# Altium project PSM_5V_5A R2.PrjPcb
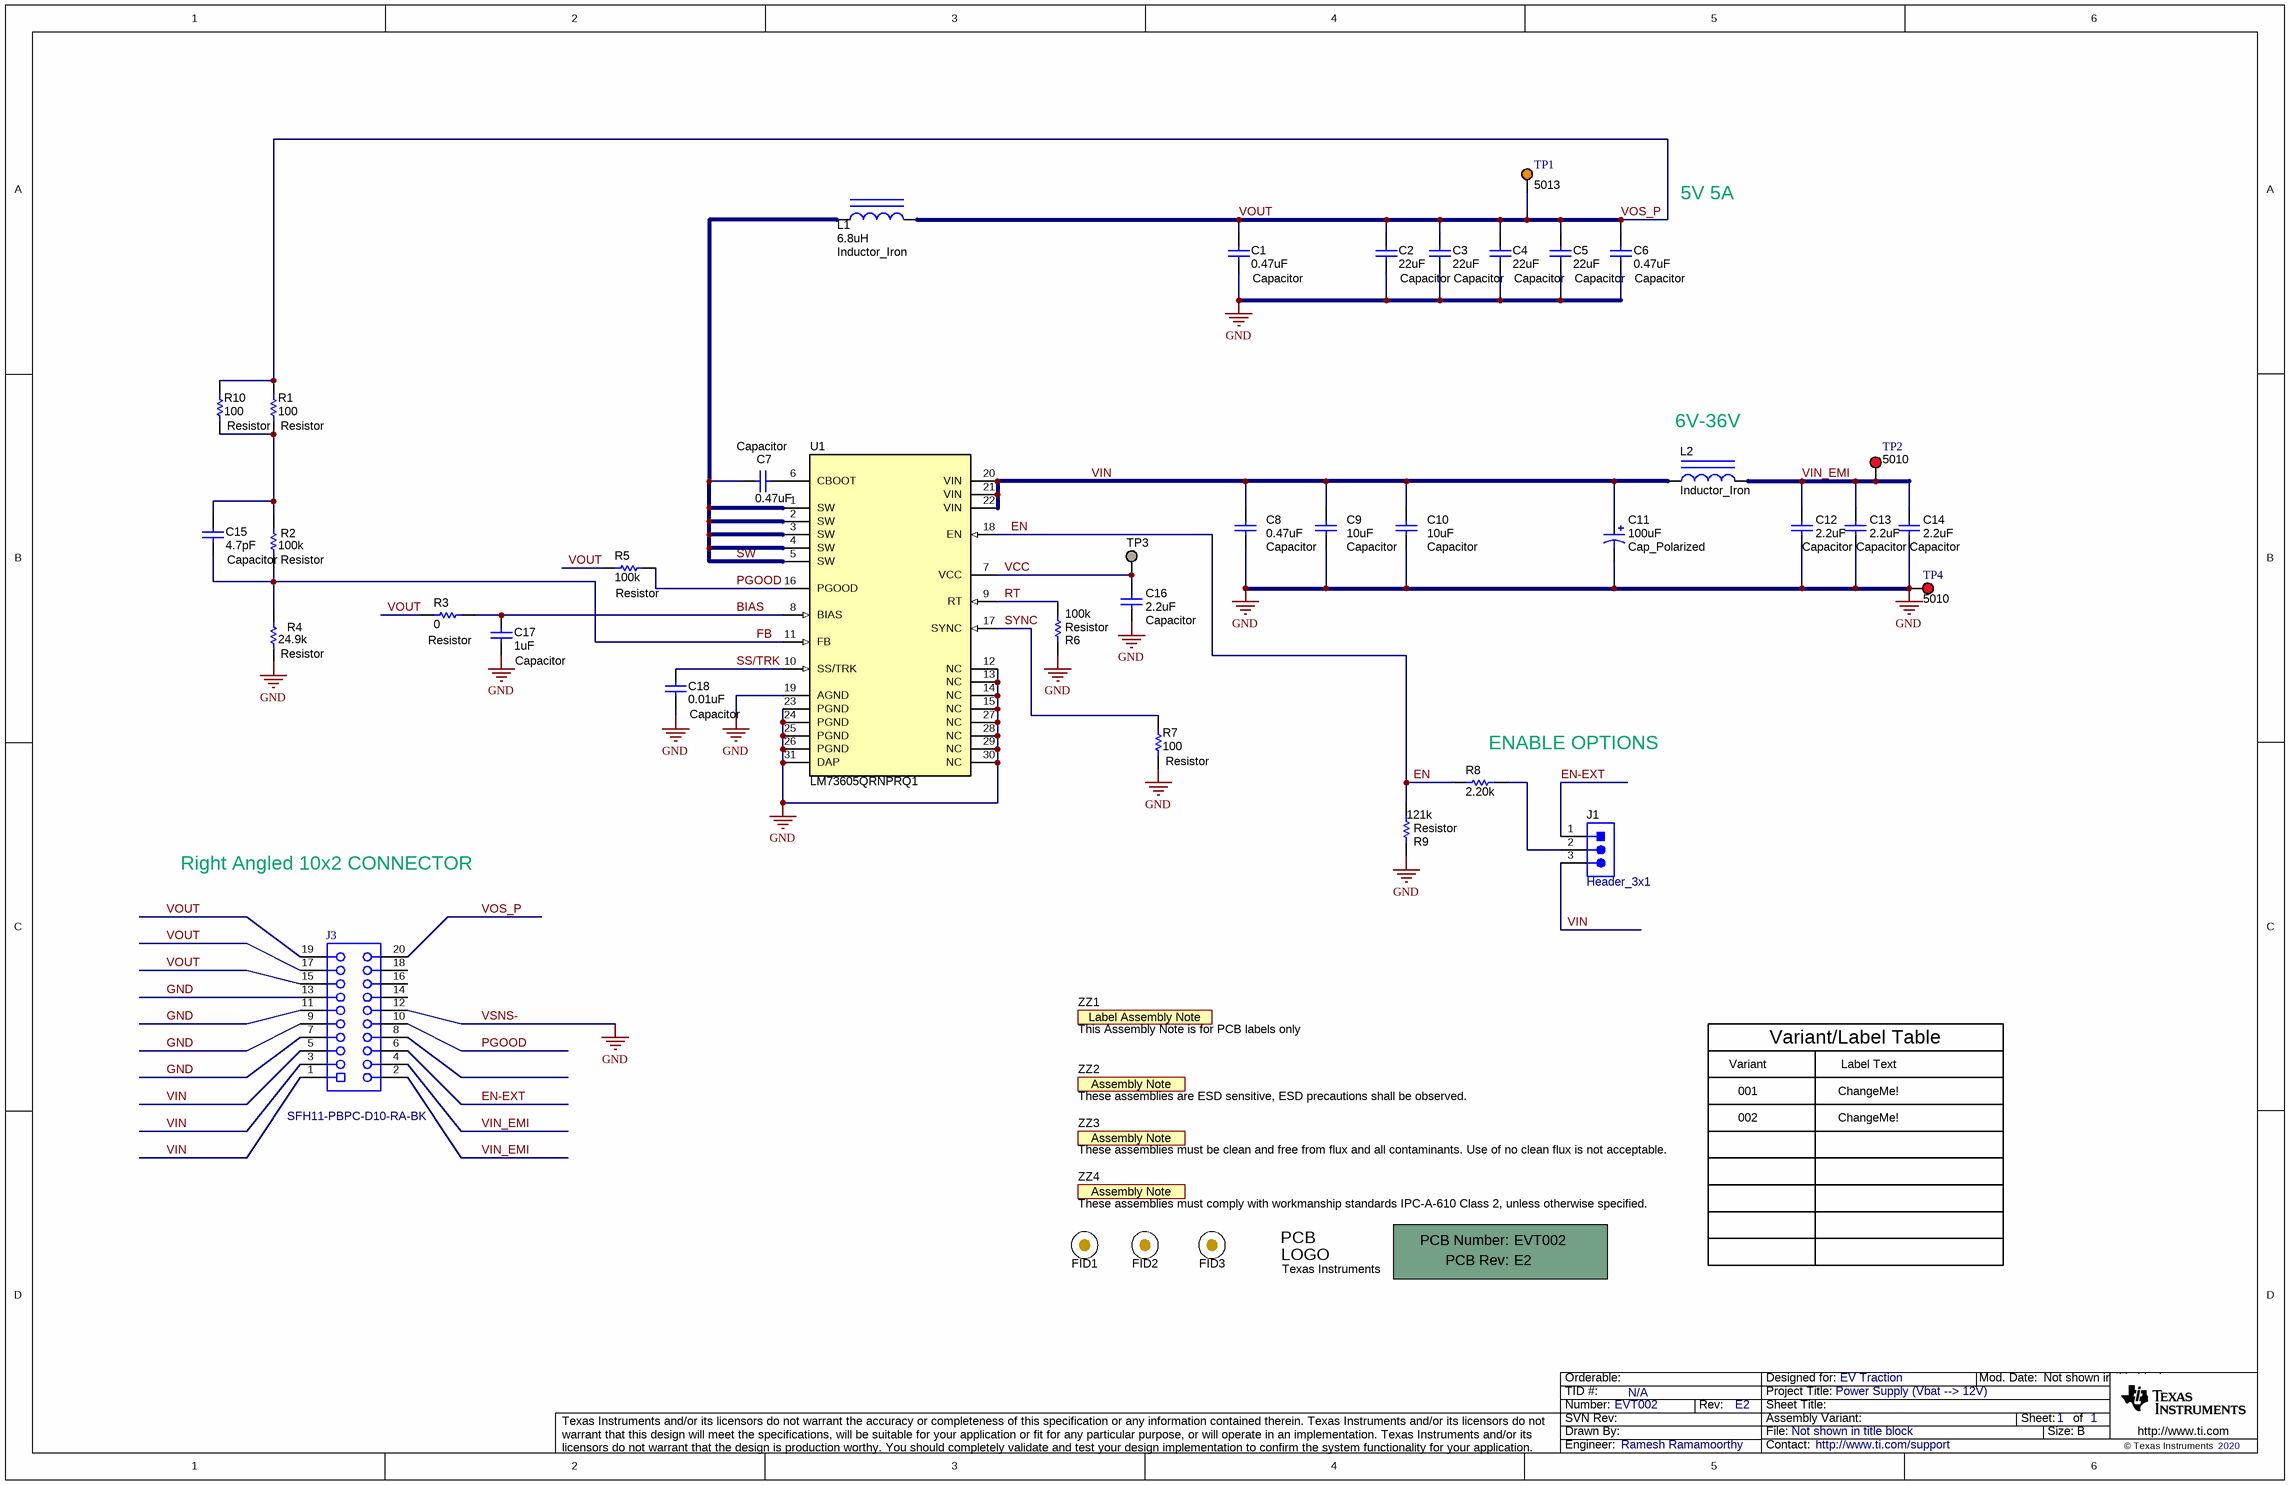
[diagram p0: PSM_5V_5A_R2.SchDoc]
CopyrightYear: 2020; PCB_Layout: Ramesh Ramamoorthy; PCB_Rev: E2; PRJ_Customer: EV Traction; PRJ_Engineer: Ramesh Ramamoorthy; PRJ_Number: EVT002; PRJ_Title: Power Supply (Vbat --> 12V); SCH_Rev: E2; TechSupport: http://www.ti.com/support; TID: N/A
1 sheet, 46 parts. Net scope: global (net labels, ports and power ports of the same name join across sheets).
Board file: PSM_5V_5A_R2_r3.PcbDoc

## Sheet PSM_5V_5A_R2.SchDoc
size 431 x 279 mm; Date: Not shown in title block; ApprovedBy: Not shown in title block; CheckedBy: Not shown in title block; Author: Not shown in title block; CompanyName: Not shown in title block; Engineer: Not shown in title block; Organization: Not shown in title block; Address1: Not shown in title block; Address2: Not shown in title block; Address3: Not shown in title block; Address4: Not shown in title block; DocumentNumber: 1; Revision: Use project parameter SCH_Rev; SheetNumber: 1; SheetTotal: 1; PageSetup: Record=PageOptions¦CenterHorizontal=True¦CenterVertical=True¦PrintScale=1.00¦XCorrection=1.00¦YCorrection=1.00¦PrintKind=0¦BorderSize=5000000¦LeftOffset=0¦BottomOffset=0¦Orientation=2¦PaperLength=1000¦PaperWidth=1000¦Scale=100¦PaperSource=15¦PrintQuality=600¦MediaType=1¦DitherType=10¦PaperKind=Letter¦PrintScaleMode=1

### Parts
!PCB1  Printed Circuit Board  (value not drawn)  (mechanical)
C1  Capacitor  ValueDisplayed: 0.47uF  [0805_HV]
C2  Capacitor  ValueDisplayed: 22uF  [1210_270]
C3  Capacitor  ValueDisplayed: 22uF  [1210_270]
C4  Capacitor  ValueDisplayed: 22uF  [1210_270]
C5  Capacitor  ValueDisplayed: 22uF  [1210_270]
C6  Capacitor  ValueDisplayed: 0.47uF  [0805_HV]
C7  Capacitor  ValueDisplayed: 0.47uF  [0603]
C8  Capacitor  ValueDisplayed: 0.47uF  [0805_HV]
C9  Capacitor  ValueDisplayed: 10uF  [1210_270]
C10  Capacitor  ValueDisplayed: 10uF  [1210_270]
C11  Cap_Polarized  ValueDisplayed: 100uF  [SM_RADIAL_G]
C12  Capacitor  ValueDisplayed: 2.2uF  [1206_180]
C13  Capacitor  ValueDisplayed: 2.2uF  [1206_180]
C14  Capacitor  ValueDisplayed: 2.2uF  [1206_180]
C15  Capacitor  ValueDisplayed: 4.7pF  [0603]
C16  Capacitor  ValueDisplayed: 2.2uF  [0603]
C17  Capacitor  ValueDisplayed: 1uF  [0603]
C18  Capacitor  ValueDisplayed: 0.01uF  [0603]
FID1  Fiducial  [Fiducial10-20]  (value not drawn)
FID2  Fiducial  [Fiducial10-20]  (value not drawn)
FID3  Fiducial  [Fiducial10-20]  (value not drawn)
J1  Header_3x1  [Samtec_HTSW-103-07-G-S]
J3  SFH11-PBPC-D10-RA-BK  [Sullins_SFH11-xxxC-D10-RA]
L1  Inductor_Iron  ValueDisplayed: 6.8uH  [XAL7070]
L2  Inductor_Iron  [XAL7030]
Logo1  Texas Instruments  [TI_Symbol_Overlay_Small]  (no BOM)
R1  Resistor  ValueDisplayed: 100  [0805_HV]
R2  Resistor  ValueDisplayed: 100k  [0603]
R3  Resistor  ValueDisplayed: 0  [0603]
R4  Resistor  ValueDisplayed: 24.9k  [0603]
R5  Resistor  ValueDisplayed: 100k  [0603]
R6  Resistor  ValueDisplayed: 100k  [0603]
R7  Resistor  ValueDisplayed: 100  [0603]
R8  ValueDisplayed: 2.20k  [0805_HV]  (hidden comment: RG2012P-222-B-T5)
R9  Resistor  ValueDisplayed: 121k  [0805_HV]
R10  Resistor  ValueDisplayed: 100  [0805_HV]
TP1  5013  [Keystone5013]
TP2  5010  [Keystone5010]
TP3  TP_H0.45P0.75  [TP_H045P075]  (value not drawn)  (no BOM)
TP4  5010  [Keystone5010]
U1  LM73605QRNPRQ1  [RNP0030A]
ZZ1  This Assembly Note is for PCB labels only  [AssemblyNoteLabel]  (no BOM)
ZZ2  These assemblies are ESD sensitive, ESD precautions shall be observed.  [AssemblyNote]  (no BOM)
ZZ3  These assemblies must be clean and free from flux and all contaminants. Use of no clean flux is not acceptable.  [AssemblyNote]  (no BOM)
ZZ4  These assemblies must comply with workmanship standards IPC-A-610 Class 2, unless otherwise specified.  [AssemblyNote]  (no BOM)

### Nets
GND: C1.1 C2.2 C3.2 C4.2 C5.2 C6.1 C8.1 C9.1 C10.1 C11.2(-) C12.2 C13.2 C14.2 C16.2 C17.2 C18.2 J3.7 J3.9 J3.11 J3.12 J3.13 R4.1 R6.2 R7.1 R9.1 TP4.1 U1.12(NC) U1.13(NC) U1.14(NC) U1.15(NC) U1.19(AGND) U1.23(PGND) U1.24(PGND) U1.25(PGND) U1.26(PGND) U1.27(NC) U1.28(NC) U1.29(NC) U1.30(NC) U1.31(DAP)  [also labelled VSNS-]
BIAS: C17.1 R3.2 U1.8(BIAS)
EN: R8.1 R9.2 U1.18(EN)
EN-EXT: J1.1 J3.6
FB: C15.2 R2.1 R4.2 U1.11(FB)
PGOOD: J3.10 R5.2 U1.16(PGOOD)
RT: R6.1 U1.9(RT)
SS/TRK: C18.1 U1.10(SS/TRK)
SW: C7.1 L1.1 U1.1(SW) U1.2(SW) U1.3(SW) U1.4(SW) U1.5(SW)
SYNC: R7.2 U1.17(SYNC)
VCC: C16.1 TP3.1 U1.7(VCC)
VIN: C8.2 C9.2 C10.2 C11.1(+) J1.3 J3.1 J3.3 J3.5 L2.1 U1.20(VIN) U1.21(VIN) U1.22(VIN)
VIN_EMI: C12.1 C13.1 C14.1 J3.2 J3.4 L2.2 TP2.1
VOS_P: C1.2 C2.1 C3.1 C4.1 C5.1 C6.2 J3.15 J3.17 J3.19 J3.20 L1.2 R1.2 R3.1 R5.1 R10.2 TP1.1  [also labelled VOUT]
NetC7_2: C7.2 U1.6(CBOOT)
NetC15_1: C15.1 R1.1 R2.2 R10.1
NetJ1_2: J1.2 R8.2

Not connected (* = marked no-connect by the designer): J3 8 14 16 18

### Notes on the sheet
- 5V 5A
- (near L2) 6V-36V
- (near R8) ENABLE OPTIONS
- Right Angled 10x2 CONNECTOR
- Variant/Label Table
- Variant
- 001
- Label Text
- ChangeMe!
- 002

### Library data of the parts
!PCB1 = CMP-0003618-2: Manufacturer: Any; PartNumber: EVT002
C1 C6 C8 = CMP-0008357-2: CAP, CERM, 0.47 uF, 50 V, +/- 10%, X7R, 0805; PartNumber: GRM21BR71H474KA88L; Manufacturer: MuRata; Polarized: N; Value: 0.47uF; U/M: EA; Cap_F: 470nF; Value1: Unknown; VDC_V: 50V; TaMin_C: -55°C; TaMax_C: 125°C; Cap_Case: 0805; AEC Category: Q200; SizeArea_mm2: 2.5; SizeAreaWB_mm2: 6.75; SizeX_mm: 2; SizeY_mm: 1.25; SizeZ_mm: 1.45
C2-C5 = CMP-0009222-2: CAP, CERM, 22 uF, 16 V, +/- 10%, X7R, 1210; PartNumber: GRM32ER71C226KE18L; Manufacturer: MuRata; Polarized: N; Value: 22uF; U/M: EA; Cap_F: 22µF; ESR_ohm: 3m; Value1: 0.003 ohm; VDC_V: 16V; TaMin_C: -55°C; TaMax_C: 125°C; Cap_Case: 1210; AEC Category: Q200; SizeArea_mm2: 8; SizeAreaWB_mm2: 14.7; SizeX_mm: 3.2; SizeY_mm: 2.5; SizeZ_mm: 2.7
C7 = CMP-0007346-5: CAP, CERM, 0.47 uF, 25 V, +/- 10%, X5R, 0603; PartNumber: GRM188R61E474KA12D; Manufacturer: MuRata; Polarized: N; Value: 0.47uF; U/M: EA; Cap_F: 470nF; Value1: Unknown; VDC_V: 25V; TaMin_C: -55°C; TaMax_C: 85°C; AEC Category: Q200; SizeArea_mm2: 1.28; SizeAreaWB_mm2: 4.68; SizeX_mm: 1.6; SizeY_mm: 0.8; SizeZ_mm: 1
C9 C10 = CMP-0009226-3: CAP, CERM, 10 uF, 50 V, +/- 10%, X7R, 1210; PartNumber: GRM32ER71H106KA12L; Manufacturer: MuRata; Polarized: N; Value: 10uF; U/M: EA; Cap_F: 10µF; Value1: Unknown; VDC_V: 50V; TaMin_C: -55°C; TaMax_C: 125°C; Cap_Case: 1210; AEC Category: Q200; SizeArea_mm2: 8; SizeAreaWB_mm2: 14.7; SizeX_mm: 3.2; SizeY_mm: 2.5; SizeZ_mm: 2.7
C11 = CMP-0011188-2: CAP, AL, 100 uF, 63 V, +/- 20%, 0.35 ohm, AEC-Q200 Grade 2, SMD; PartNumber: EEE-FK1J101P; Manufacturer: Panasonic; Polarized: Y; CompType: Capacitor; Value: 100uF; U/M: EA; Cap_F: 100µF; VDC_V: 63V; ESR_ohm: 0.35; IRMS_A: 400mA; TaMin_C: -55°C; TaMax_C: 105°C; Cap_Case: G; AEC Category: Q200; AEC Grade: 2; SizeArea_mm2: 123.6; SizeAreaWB_mm2: 172.2; SizeX_mm: 12; SizeY_mm: 10.3; SizeZ_mm: 10.2
C12-C14 = CMP-0008955-2: CAP, CERM, 2.2 uF, 50 V, +/- 10%, X5R, 1206; PartNumber: GRM31CR61H225KA88L; Manufacturer: MuRata; Polarized: N; Value: 2.2uF; U/M: EA; Cap_F: 2.2µF; Value1: Unknown; VDC_V: 50V; TaMin_C: -55°C; TaMax_C: 85°C; Cap_Case: 1206; AEC Category: Q200; SizeArea_mm2: 5.12; SizeAreaWB_mm2: 10.92; SizeX_mm: 3.2; SizeY_mm: 1.6; SizeZ_mm: 1.8
C15 = CMP-0006791-4: CAP, CERM, 4.7 pF, 50 V, +/- 5%, C0G/NP0, 0603; PartNumber: 06035A4R7CAT2A; Manufacturer: AVX; Polarized: N; Value: 4.7pF; U/M: EA; ESR_ohm: 0.633; Value1: 0.633 ohm; VDC_V: 50V; TaMin_C: -55°C; TaMax_C: 125°C; AEC Category: Q200; SizeArea_mm2: 1.28; SizeAreaWB_mm2: 4.68; SizeX_mm: 1.6; SizeY_mm: 0.8; SizeZ_mm: 1
C16 = CMP-0007296-4: CAP, CERM, 2.2 uF, 10 V, +/- 10%, X6S, 0603; PartNumber: GRM188C81A225KE34D; Manufacturer: MuRata; Polarized: N; Value: 2.2uF; U/M: EA; Cap_F: 2.2µF; Value1: Unknown; VDC_V: 10V; TaMin_C: -55°C; TaMax_C: 105°C; AEC Category: Q200; SizeArea_mm2: 1.28; SizeAreaWB_mm2: 4.68; SizeX_mm: 1.6; SizeY_mm: 0.8; SizeZ_mm: 1
C17 = CMP-0006867-4: CAP, CERM, 1 uF, 25 V, +/- 10%, X7R, 0603; PartNumber: C0603C105K3RACTU; Manufacturer: Kemet; Polarized: N; Value: 1uF; U/M: EA; Cap_F: 1µF; Value1: Unknown; VDC_V: 25V; TaMin_C: -55°C; TaMax_C: 125°C; SizeArea_mm2: 1.28; SizeAreaWB_mm2: 4.68; SizeX_mm: 1.6; SizeY_mm: 0.8; SizeZ_mm: 1; AEC Category: Q200
C18 = CMP-0006728-5: CAP, CERM, 0.01 uF, 100 V, +/- 20%, X7R, 0603; PartNumber: 06031C103MAT2A; Manufacturer: AVX; Polarized: N; Value: 0.01uF; U/M: EA; Cap_F: 10nF; ESR_ohm: 0.098; Value1: 0.098 ohm; VDC_V: 100V; TaMin_C: -55°C; TaMax_C: 125°C; AEC Category: Q200; SizeArea_mm2: 1.28; SizeAreaWB_mm2: 4.68; SizeX_mm: 1.6; SizeY_mm: 0.8; SizeZ_mm: 1
FID1-FID3 = CMP-0077181-1: Fiducial mark.  There is nothing to buy or mount.
J1 = CMP-0075484-1: Header, 100mil, 3x1, Gold, TH; PartNumber: HTSW-103-07-G-S; Manufacturer: Samtec; CNHeader: True; CT: False; Green_Lifecycle: Active; Green_REACh: Passed
J3 = CMP-0074634-1: Receptacle, 2.54mm, 10x2, Gold, R/A, TH; Manufacturer: Sullins Connector Solutions; CNHeader: False; Current_A: 3A; Gender: Female; Voltage_V: 1kV; CompType: Socket Strip; Row_Count: 2; Pitch_mm: 2.54; CT: True; Cert_UL: Y
L1 = CMP-0061057-1: Inductor, Shielded, Composite, 6.8 uH, 9.2 A, 0.02 ohm, SMD; PartNumber: XAL7070-682MEB; Manufacturer: Coilcraft; Value: 6.8uH; Ind_H: 6.8µH; Imax_A: 9.2A; Irms: 9.2A @ 40C rise; Isat: 12.8A @ 30% inductance drop; DCR_ohm: 0.02; AEC Category: Q200; Green_Lifecycle: Not Set; Green_REACh: Incomplete; SizeArea_mm2: 54; SizeAreaWB_mm2: 87.4; SizeX_mm: 7.2; SizeY_mm: 7.5; SizeZ_mm: 7
L2 = CMP-0061037-1: Inductor, Shielded, Composite, 2.2 uH, 12.9 A, 0.0137 ohm, SMD; PartNumber: XAL7030-222MEB; Manufacturer: Coilcraft; Value: 2.2uH; Ind_H: 2.2µH; Imax_A: 12.9A; Irms: 12.9A @ 40C rise; Isat: 18A @ 0.7% inductance drop; DCR_ohm: 0.0137; AEC Category: Q200; Green_Lifecycle: Not Set; Green_REACh: Incomplete; SizeArea_mm2: 64; SizeAreaWB_mm2: 100; SizeX_mm: 8; SizeZ_mm: 3.1
Logo1 = CMP-0074838-1: Texas Instrument Corporate Signature; SymbolCreator: a0412235; Lib Reference: TI_Logo; Library Reference: Logo
R1 R10 = CMP-0020835-3: RES, 100, 1%, 0.125 W, AEC-Q200 Grade 0, 0805; PartNumber: CRCW0805100RFKEA; Manufacturer: Vishay-Dale; Value: 100; Value_Code: 100R; Power_W: 125mW; Value2: 0.125W; VDC_V: 150V; TempCo: 100 ppm/C; EIA_Code: E96; AEC Category: Q200; AEC Qualified: Y; AEC Grade: 0; SizeArea_mm2: 2.5; SizeX_mm: 2; SizeY_mm: 1.25; SizeZ_mm: 1.45
R2 R6 = CMP-0021990-4: RES, 100 k, 1%, 0.1 W, AEC-Q200 Grade 0, 0603; PartNumber: CRCW0603100KFKEA; Manufacturer: Vishay-Dale; Value: 100k; Power_W: 100mW; Value2: 0.1W; VDC_V: 75V; TempCo: 100 ppm/C; SizeArea_mm2: 1.28; SizeX_mm: 1.6; SizeY_mm: 0.8; SizeZ_mm: 1; EIA_Code: E96; AEC Category: Q200; AEC Qualified: Y; AEC Grade: 0
R3 = CMP-0025697-4: RES, 0, 5%, 0.1 W, AEC-Q200 Grade 0, 0603; PartNumber: CRCW06030000Z0EA; Manufacturer: Vishay-Dale; Value: 0; Value_Code: 0000; Power_W: 100mW; Value2: 0.1W; VDC_V: 75V; TempCo: 200 ppm/C; EIA_Code: E24; AEC Category: Q200; AEC Qualified: Y; SizeArea_mm2: 1.28; SizeX_mm: 1.6; SizeY_mm: 0.8; SizeZ_mm: 1
R4 = CMP-0022237-4: RES, 24.9 k, 1%, 0.1 W, AEC-Q200 Grade 0, 0603; PartNumber: CRCW060324K9FKEA; Manufacturer: Vishay-Dale; Value: 24.9k; Value_Code: 24k9; Power_W: 100mW; Value2: 0.1W; VDC_V: 75V; TempCo: 100 ppm/C; SizeArea_mm2: 1.28; SizeX_mm: 1.6; SizeY_mm: 0.8; SizeZ_mm: 1; EIA_Code: E96; AEC Category: Q200; AEC Qualified: Y; AEC Grade: 0
R5 = CMP-0021990-4: RES, 100 k, 1%, 0.1 W, AEC-Q200 Grade 0, 0603; PartNumber: CRCW0603100KFKEA; Manufacturer: Vishay-Dale; Value: 100k; Power_W: 100mW; Value2: 0.1W; VDC_V: 75V; TempCo: 100 ppm/C; EIA_Code: E96; AEC Category: Q200; AEC Grade: 0; AEC Qualified: Y; SizeArea_mm2: 1.28; SizeX_mm: 1.6; SizeY_mm: 0.8; SizeZ_mm: 1
R7 = CMP-0021991-4: RES, 100, 1%, 0.1 W, AEC-Q200 Grade 0, 0603; PartNumber: CRCW0603100RFKEA; Manufacturer: Vishay-Dale; Value: 100; Value_Code: 100R; Power_W: 100mW; Value2: 0.1W; VDC_V: 75V; TempCo: 100 ppm/C; SizeArea_mm2: 1.28; SizeX_mm: 1.6; SizeY_mm: 0.8; SizeZ_mm: 1; EIA_Code: E96; AEC Category: Q200; AEC Qualified: Y; AEC Grade: 0
R8 = CMP-0018920-1: RES, 2.20 k, 0.1%, 0.125 W, 0805; Manufacturer: Susumu Co Ltd; Power_W: 125mW; TempCo: 25 ppm/C; Value_Code: 2k20; U/M: EA; Value: 2.20k; Res_ohm: 2.2k; SizeX_mm: 2; SizeY_mm: 1.25; SizeZ_mm: 1.45; Value2: 0.125W; SizeArea_mm2: 2.5; VDC_V: 100V; AEC Category: Q200
R9 = CMP-0020867-3: RES, 121 k, 1%, 0.125 W, AEC-Q200 Grade 0, 0805; PartNumber: CRCW0805121KFKEA; Manufacturer: Vishay-Dale; Value: 121k; Power_W: 125mW; Value2: 0.125W; VDC_V: 150V; TempCo: 100 ppm/C; EIA_Code: E96; AEC Category: Q200; AEC Grade: 0; AEC Qualified: Y; SizeArea_mm2: 2.5; SizeX_mm: 2; SizeY_mm: 1.25; SizeZ_mm: 1.45
TP1 = CMP-0055150-1: Test Point, Multipurpose, Orange, TH; Manufacturer: Keystone; CNHeader: FALSE; ContactFinish: Silver; CT: TRUE; Green_Lifecycle: Active; Green_REACh: Passed
TP2 TP4 = CMP-0055147-1: Test Point, Multipurpose, Red, TH; Manufacturer: Keystone; CNHeader: FALSE; ContactFinish: Silver; CT: TRUE; Green_Lifecycle: Active; Green_REACh: Passed
TP3 = CMP-0003719-1: Testpoint; Manufacturer: Texas Instruments; CompType: Pad
U1 = CMP-0013936-4: Automotive 3.5V to 36V 5A Synchronous Step-Down Voltage Regulator, RNP0030A (WQFN-30); Manufacturer: Texas Instruments; Alternate PartNumber: LM73605QRNPTQ1; SizeX_mm: 4; SizeY_mm: 6; CompType: IC; SizeZ_mm: 0.8; SizeArea_mm2: 24; SizeAreaWB_mm2: 48; AEC Category: Q200; AEC Qualified: Y
ZZ1 = CMP-0003616-3
ZZ2 = CMP-0077236-1
ZZ3 = CMP-0077237-1
ZZ4 = CMP-0077238-1

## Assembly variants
001: not fitted FID1 FID2 FID3 R1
